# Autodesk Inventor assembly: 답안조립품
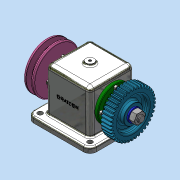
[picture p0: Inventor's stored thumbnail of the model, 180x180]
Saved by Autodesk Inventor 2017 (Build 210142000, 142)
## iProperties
Part Number: 답안조립품
Material: 일반
Document SubType Name: Assembly
Designer: MRC
Author: MRC
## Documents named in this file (12)
- C:\Users\MRC\Desktop\720706V1018\답안조립품.iam
- C:\Users\MRC\Desktop\720706V1018\V벨트풀리.ipt
- C:\Users\MRC\Desktop\720706V1018\너트 M12x1.25.ipt
- C:\Users\MRC\Desktop\720706V1018\베어링 6204.ipt
- C:\Users\MRC\Desktop\720706V1018\본체.ipt
- C:\Users\MRC\Desktop\720706V1018\볼트 M4x0.7.ipt
- C:\Users\MRC\Desktop\720706V1018\스퍼기어.ipt
- C:\Users\MRC\Desktop\720706V1018\오일실 20x35x8.ipt
- C:\Users\MRC\Desktop\720706V1018\와셔 12x24.ipt
- C:\Users\MRC\Desktop\720706V1018\축.ipt
- C:\Users\MRC\Desktop\720706V1018\커버.ipt
- C:\Users\MRC\Desktop\720706V1018\키 5x5.ipt
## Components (1 placed, 1 different names)
1. V벨트풀리:1
